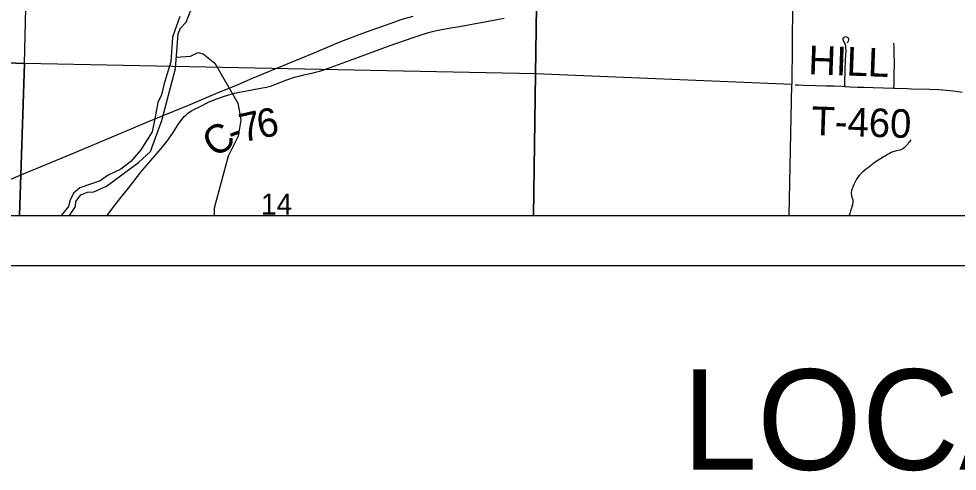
# Model space of a CAD drawing. Extents: x 0 to 34, y 0 to 22.
# Drawn here: x 2.935 to 4.8, y 13.591 to 14.491 of the extents above; entities that cross this region are included whole.
import ezdxf

# ---------------------------------------------------------------- set-up
doc = ezdxf.new("R2010")
doc.units = 0
for name, color, linetype in [('GM_X_Corporation', 7, 'Continuous'), ('GM_X_County_Road', 7, 'Continuous'), ('GM_X_County_Road_Text', 7, 'Continuous'), ('GM_X_Minor_River', 7, 'Continuous'), ('GM_X_Rail_Line', 7, 'Continuous'), ('GM_X_Section_Text', 7, 'Continuous'), ('GM_X_Township_Road', 7, 'Continuous'), ('GM_X_Township_Road_Text', 7, 'Continuous'), ('SH_Data', 7, 'Continuous'), ('SH_Text', 7, 'Continuous')]:
    doc.layers.add(name, color=color, linetype=linetype)

msp = doc.modelspace()

# ---------------------------------------------------------------- linework, layer by layer
at = {"layer": 'GM_X_Corporation'}
for points in [[(2.1, 16.4477), (2.1, 14.1), (8.9, 14.1), (8.9, 16.2485)], [(2.1155, 16.4201), (2.1, 15.9517), (2.1, 14.1), (5.9669, 14.1)]]:
    msp.add_lwpolyline(points, dxfattribs=at)
for points in [[(2.1, 15.4549), (2.1, 14.4331), (2.9463, 14.4019), (2.9706, 15.4194)], [(2.9706, 15.4194), (3.9769, 15.3648), (3.9619, 14.3814), (2.9463, 14.4019)], [(3.9769, 15.3648), (4.4816, 15.354), (4.4815, 15.3372), (4.4758, 14.8389), (4.4713, 14.3604), (3.9619, 14.3814)], [(2.1, 14.4331), (2.1, 14.1), (2.9364, 14.1), (2.9463, 14.4019)], [(2.9364, 14.1), (3.9581, 14.1), (3.9619, 14.3814), (2.9463, 14.4019)], [(3.9581, 14.1), (4.4665, 14.1), (4.4713, 14.3604), (3.9619, 14.3814)]]:
    msp.add_lwpolyline(points, close=True, dxfattribs=at)
at = {"layer": 'GM_X_County_Road'}
msp.add_lwpolyline([(3.1104, 14.1), (3.1237, 14.1179), (3.1413, 14.1396), (3.1528, 14.1539), (3.1774, 14.1857), (3.1839, 14.1937), (3.1934, 14.2047), (3.222, 14.2374), (3.2315, 14.2496), (3.2417, 14.2651), (3.2517, 14.2808), (3.2611, 14.2933), (3.2637, 14.2965), (3.2675, 14.3001), (3.2706, 14.3028), (3.2748, 14.306), (3.278, 14.308), (3.2829, 14.3108), (3.2939, 14.3163), (3.3137, 14.3257), (3.3287, 14.332), (3.3456, 14.338), (3.3636, 14.3429), (3.3736, 14.3453), (3.3881, 14.348), (3.4016, 14.3505), (3.4195, 14.3537), (3.4274, 14.3554), (3.4351, 14.3574), (3.4442, 14.3605), (3.468, 14.3699), (3.4828, 14.3747), (3.4918, 14.3773), (3.5045, 14.3803), (3.5201, 14.3836), (3.5248, 14.3848), (3.533, 14.3869), (3.5396, 14.389), (3.5488, 14.392), (3.5924, 14.4083), (3.671, 14.4373), (3.7208, 14.4548), (3.7326, 14.4586), (3.7475, 14.4631), (3.7572, 14.4658), (3.7686, 14.4685), (3.7789, 14.4708), (3.7899, 14.4727), (3.8144, 14.4768), (3.8571, 14.4846), (3.8999, 14.4925)], dxfattribs=at)
at = {"layer": 'GM_X_Minor_River'}
for points in [[(3.2549, 14.4957), (3.2448, 14.4676), (3.2403, 14.4546), (3.2371, 14.4053), (3.2237, 14.3625), (3.2188, 14.3396), (3.2114, 14.3247), (3.2069, 14.2997), (3.1998, 14.2663), (3.1777, 14.2302), (3.1577, 14.207), (3.1381, 14.1917), (3.1124, 14.1799), (3.0965, 14.1688), (3.0565, 14.155), (3.044, 14.1444), (3.0365, 14.1292), (3.0339, 14.1174), (3.019, 14.1)], [(3.0358, 14.1), (3.0479, 14.1174), (3.0486, 14.1277), (3.0584, 14.141), (3.0713, 14.1463), (3.0841, 14.1468), (3.1095, 14.1579), (3.1732, 14.2055), (3.1966, 14.2268), (3.219, 14.2888), (3.2466, 14.3921), (3.252, 14.4615), (3.2565, 14.4722), (3.2674, 14.4843), (3.2768, 14.5083)], [(3.0358, 14.1), (3.0479, 14.1174), (3.0486, 14.1277), (3.0584, 14.141), (3.0713, 14.1463), (3.0841, 14.1468), (3.1095, 14.1579), (3.1732, 14.2055), (3.1966, 14.2268), (3.219, 14.2888), (3.2466, 14.3921), (3.252, 14.4615), (3.2565, 14.4722), (3.2674, 14.4843), (3.2768, 14.5083)], [(3.2484, 14.4146), (3.2765, 14.4168), (3.2912, 14.4241), (3.3015, 14.4215), (3.3247, 14.403), (3.3702, 14.3236), (3.3741, 14.3023), (3.376, 14.2894), (3.3708, 14.2576), (3.3513, 14.218), (3.323, 14.1143), (3.3233, 14.1)]]:
    msp.add_lwpolyline(points, dxfattribs=at)
msp.add_open_spline([(4.709, 14.2506), (4.7059, 14.2469), (4.7028, 14.2432), (4.6996, 14.2396), (4.6908, 14.2292), (4.6748, 14.2284), (4.663, 14.2216), (4.6509, 14.2146), (4.6393, 14.2074), (4.6279, 14.1987), (4.6125, 14.1871), (4.5993, 14.173), (4.5921, 14.155), (4.5873, 14.1429), (4.5944, 14.1291), (4.5908, 14.117), (4.5891, 14.1113), (4.5873, 14.1056), (4.5852, 14.1)], degree=3, dxfattribs=at)
at = {"layer": 'GM_X_Rail_Line'}
msp.add_lwpolyline([(2.867, 14.1504), (2.9409, 14.1812), (3.0481, 14.226), (3.1927, 14.2865), (3.2754, 14.3207), (3.3264, 14.3423), (3.3712, 14.3607), (3.3993, 14.3728), (3.4448, 14.3915), (3.5218, 14.4237), (3.5483, 14.4347), (3.5719, 14.4445), (3.5946, 14.4533), (3.624, 14.4646), (3.6483, 14.4731), (3.673, 14.4816), (3.6972, 14.4902), (3.7191, 14.4967)], dxfattribs=at)
at = {"layer": 'GM_X_Township_Road'}
for points in [[(4.5766, 14.3567), (4.5768, 14.3631), (4.5776, 14.3903), (4.5784, 14.4087), (4.5793, 14.4271), (4.5791, 14.4332), (4.5787, 14.4363), (4.5779, 14.4392), (4.5742, 14.4478), (4.5737, 14.4496), (4.5737, 14.4508), (4.5738, 14.4523), (4.5746, 14.4535), (4.5757, 14.4545), (4.577, 14.4553), (4.5786, 14.4556), (4.58, 14.4555), (4.5815, 14.4549), (4.5827, 14.454), (4.5836, 14.4528), (4.5841, 14.4513), (4.5842, 14.4497), (4.584, 14.4483), (4.5829, 14.4454), (4.5817, 14.4426)], [(4.6745, 14.3532), (4.6747, 14.3615), (4.675, 14.3771), (4.6753, 14.4052), (4.6751, 14.4209), (4.6748, 14.4334), (4.6745, 14.4427)], [(4.4784, 14.3595), (4.4846, 14.3596), (4.4939, 14.3594), (4.5187, 14.3587), (4.5404, 14.358), (4.556, 14.3575), (4.5714, 14.3569), (4.5766, 14.3567)], [(4.5766, 14.3567), (4.5785, 14.3566), (4.5869, 14.3561), (4.6023, 14.3553), (4.6147, 14.3549), (4.6333, 14.3544), (4.6745, 14.3532)], [(4.6745, 14.3532), (4.6768, 14.3532), (4.7016, 14.3522), (4.7086, 14.3521)], [(4.7086, 14.3521), (4.7455, 14.3513), (4.7636, 14.3503), (4.7853, 14.3486), (4.7976, 14.3472), (4.8098, 14.3452)]]:
    msp.add_lwpolyline(points, dxfattribs=at)
at = {"layer": 'SH_Data'}
for p, q in [((2.1, 14.1), (8.9, 14.1)), ((2, 14), (9, 14))]:
    msp.add_line(p, q, dxfattribs=at)

# ---------------------------------------------------------------- texts
at = {"layer": 'GM_X_County_Road_Text'}
for s, rotation, p in [('7', 12.4735, (3.3801, 14.245)), ('6', 11.0119, (3.4139, 14.2525)), ('C', 34.3298, (3.3248, 14.2132)), ('-', 19.2422, (3.3598, 14.2378))]:
    msp.add_text(s, height=0.0568, rotation=rotation, dxfattribs=at).set_placement(p)
at = {"layer": 'GM_X_Section_Text'}
msp.add_text('14', height=0.04186, rotation=0, dxfattribs=at).set_placement((3.4162, 14.1016))
at = {"layer": 'GM_X_Township_Road_Text'}
for s, rotation, p in [('HILL', 357.8891, (4.5037, 14.3812)), ('T-460', 358.1276, (4.5098, 14.2602))]:
    msp.add_text(s, height=0.05682, rotation=rotation, dxfattribs=at).set_placement(p)
at = {"layer": 'SH_Text'}
msp.add_text('LOCATION MAP', height=0.2, dxfattribs=at).set_placement((4.2539, 13.5938))

doc.saveas('drawing.dxf')
